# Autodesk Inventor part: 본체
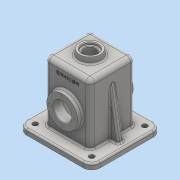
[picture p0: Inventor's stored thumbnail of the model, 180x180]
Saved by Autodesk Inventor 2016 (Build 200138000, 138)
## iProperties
Created: 2022-11
Part Number: 본체
Material: 일반
Document SubType Name: Modeling
Designer: PC-1-2
Density: 1 g/cm^3
Appearance: 기본값
Author: PC-1-2
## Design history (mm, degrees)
sketch "스케치1"
  geometry: L1 (-65, -62)-(65, -62); L2 (65, -62)-(65, 62); L3 (65, 62)-(-65, 62); L4 (-65, 62)-(-65, -62); L5 (-65, -62)-(65, 62); L6 (65, -62)-(-65, 62); 1 further point
  constraints: 12 end point, 2 midpoint, 2 parallel, 1 horizontal, 1 perpendicular
  dimensions: "d0" = 124 distance between parallel lines of L1 L3; "d1" = 130 distance between parallel lines of L2 L4
extrude "돌출1" new body sketch "스케치1" distance "d2" = 10; taper "d3" = 0 deg
sketch "스케치2"
  geometry: L1 (-40, 40)-(40, 40); L2 (40, 40)-(40, -40); L3 (40, -40)-(-40, -40); L4 (-40, -40)-(-40, 40); L5 (-40, 40)-(40, -40); L6 (40, 40)-(-40, -40); 1 further point
  constraints: 12 end point, 2 midpoint, 2 parallel, 1 horizontal, 1 perpendicular
  dimensions: "d4" = 80 distance between parallel lines of L3 L1; "d5" = 80 distance between parallel lines of L4 L2
extrude "돌출2" join sketch "스케치2" distance "d6" = 107; taper "d7" = 0 deg
sketch "스케치3"
  geometry: L1 (-65, 10)-(65, 10) reference; L2 (55, 10)-(40, 95.069); L3 (-55, 10)-(-40, 95.069); L4 (40, 10)-(40, 117) reference; L5 (-40, 10)-(-40, 117) reference; L6 (65, 0)-(65, 10) reference; L7 (-65, 0)-(-65, 10) reference; 1 further point
  constraints: 4 end point, 4 point on line
  dimensions: "d8" = 100 deg angle of L1 L2; "d9" = 100 deg angle of L1 L3; "d10" = 10 distance from line of L6 L2.start; "d11" = 10 distance from line of L7 L3.start
extrude "돌출3" join sketch "스케치3" stored distance "d12" = 10; taper "d13" = 0 deg
sketch "스케치4"
  geometry: L1 (-65, 0)-(65, 0) reference; C1 r 27.5 at (0, 55); 1 further point
  constraints: 1 centre point, 1 vertical alignment
  dimensions: "d14" = 55 diameter of C1; "d15" = 55 distance from line of L1 C1.centre
extrude "돌출4" join sketch "스케치4" stored distance "d16" = 98; taper "d17" = 0 deg
sketch "스케치5"
  geometry: C1 r 20 at (0, 0); 1 further point
  constraints: 1 centre point, 1 coincident
  dimensions: "d18" = 40 diameter of C1
extrude "돌출5" join sketch "스케치5" distance "d19" = 10; taper "d20" = 0 deg
feature "면 기울기1" dims angle "d21" = 10 deg
sketch "스케치6"
  geometry: L1 (32, 32)-(-32, 32); L2 (-32, 32)-(-32, -32); L3 (-32, -32)-(32, -32); L4 (32, -32)-(32, 32); L5 (32, 32)-(-32, -32); L6 (-32, 32)-(32, -32); 1 further point
  constraints: 12 end point, 2 midpoint, 2 parallel, 1 horizontal, 1 perpendicular
  dimensions: "d22" = 64 distance of L1.end L2.end; "d23" = 64 distance of L1.start L1.end
extrude "돌출6" cut sketch "스케치6" distance "d24" = 109; taper "d25" = 0 deg
hole "구멍1" diameter "d28" = 32; stored, may be unused: countersink angle "d32" = 90 deg, drill point angle "d34" = 118 deg; dims "d26" = 10, "d27" = 10, "d29" = 6, "d30" = 4, "d31" = 2, "d33" = 8
hole "구멍2" diameter "d37" = 21; stored, may be unused: countersink angle "d41" = 90 deg, drill point angle "d43" = 118 deg; dims "d35" = 10, "d36" = 10, "d38" = 6, "d39" = 28, "d40" = 4, "d42" = 8
sketch "스케치7" dims "d44" = 45
  geometry: C1 r 27.5 at (0, 0) reference; 3 further points
  constraints: 2 vertical alignment, 3 other
hole "구멍3" sketch "스케치7" at (0, 22.5) diameter "d45" = 3.242; stored, may be unused: countersink angle "d49" = 82 deg, drill point angle "d51" = 118 deg; dims "d46" = 8, "d47" = 3.023, "d48" = 4, "d50" = 10
sketch "스케치8"
  geometry: C1 r 22.5 at (0, 0); C2 r 27.5 at (0, 0) reference; C3 r 1.621 at (0, -22.5) reference; 2 further points
  constraints: 1 centre point, 1 coincident, 1 concentric
  dimensions: "d55" = 45 diameter of C1
hole "구멍4" sketch "스케치8" at (0, -22.5) diameter "d56" = 3.242; stored, may be unused: countersink angle "d60" = 82 deg, drill point angle "d62" = 118 deg; dims "d57" = 8, "d58" = 3.023, "d59" = 4, "d61" = 10
fillet "모깎기1" dims "d66" = 15
hole "구멍5" diameter "d69" = 9; stored, may be unused: countersink angle "d73" = 82 deg, drill point angle "d75" = 0 deg; dims "d67" = 10, "d68" = 10, "d70" = 8, "d71" = 3.023, "d72" = 4, "d74" = 15
hole "구멍6" diameter "d78" = 9; stored, may be unused: countersink angle "d82" = 82 deg, drill point angle "d84" = 0 deg; dims "d76" = 10, "d77" = 10, "d79" = 8, "d80" = 3.023, "d81" = 4, "d83" = 15
hole "구멍7" diameter "d87" = 9; stored, may be unused: countersink angle "d91" = 82 deg, drill point angle "d93" = 0 deg; dims "d85" = 10, "d86" = 10, "d88" = 8, "d89" = 3.023, "d90" = 4, "d92" = 15
hole "구멍8" diameter "d96" = 9; stored, may be unused: countersink angle "d100" = 82 deg, drill point angle "d102" = 0 deg; dims "d94" = 10, "d95" = 10, "d97" = 8, "d98" = 3.023, "d99" = 4, "d101" = 15
fillet "모깎기2" dims "d103" = 3
fillet "모깎기3" dims "d104" = 8
fillet "모깎기4" dims "d105" = 3
fillet "모깎기5" dims "d106" = 3
fillet "모깎기6" dims "d107" = 3
fillet "모깎기7" dims "d108" = 3
fillet "모깎기8" dims "d109" = 3
fillet "모깎기9" dims "d110" = 8
fillet "모깎기10" dims "d111" = 3
fillet "모깎기11" dims "d112" = 3
fillet "모깎기12" dims "d113" = 3
fillet "모깎기13" dims "d114" = 3
chamfer "모따기1" distance "d115" = 1; stored, may be unused: second distance "d116" = 2, angle "d117" = 45 deg
sketch "스케치9"
  geometry: L1 (12, 92)-(52, 92); L2 (52, 92)-(52, 86); L3 (52, 86)-(12, 86); L4 (12, 86)-(12, 92); L5 (12, 89)-(52, 89); L6 (32, 92)-(32, 86); L7 (-18, -13)-(82, -13) reference; L8 (50.237, 114)-(13.763, 114) reference; 3 further points
  constraints: 6 midpoint, 4 end point, 1 vertical, 1 vertical alignment, 2 other
  dimensions: "d118" = 6 distance between parallel lines of L3 L1; "d119" = 40 distance between parallel lines of L4 L2; "d120" = 25 distance between parallel lines of L8 L5
feature "엠보싱1" sketch "스케치9" dims "d121" = 0.5, "d122" = 0
node "솔리드1"
pattern_circular "원형 패턴1" dims angle "d53" = 360 deg
pattern_circular "원형 패턴2" dims angle "d64" = 360 deg
